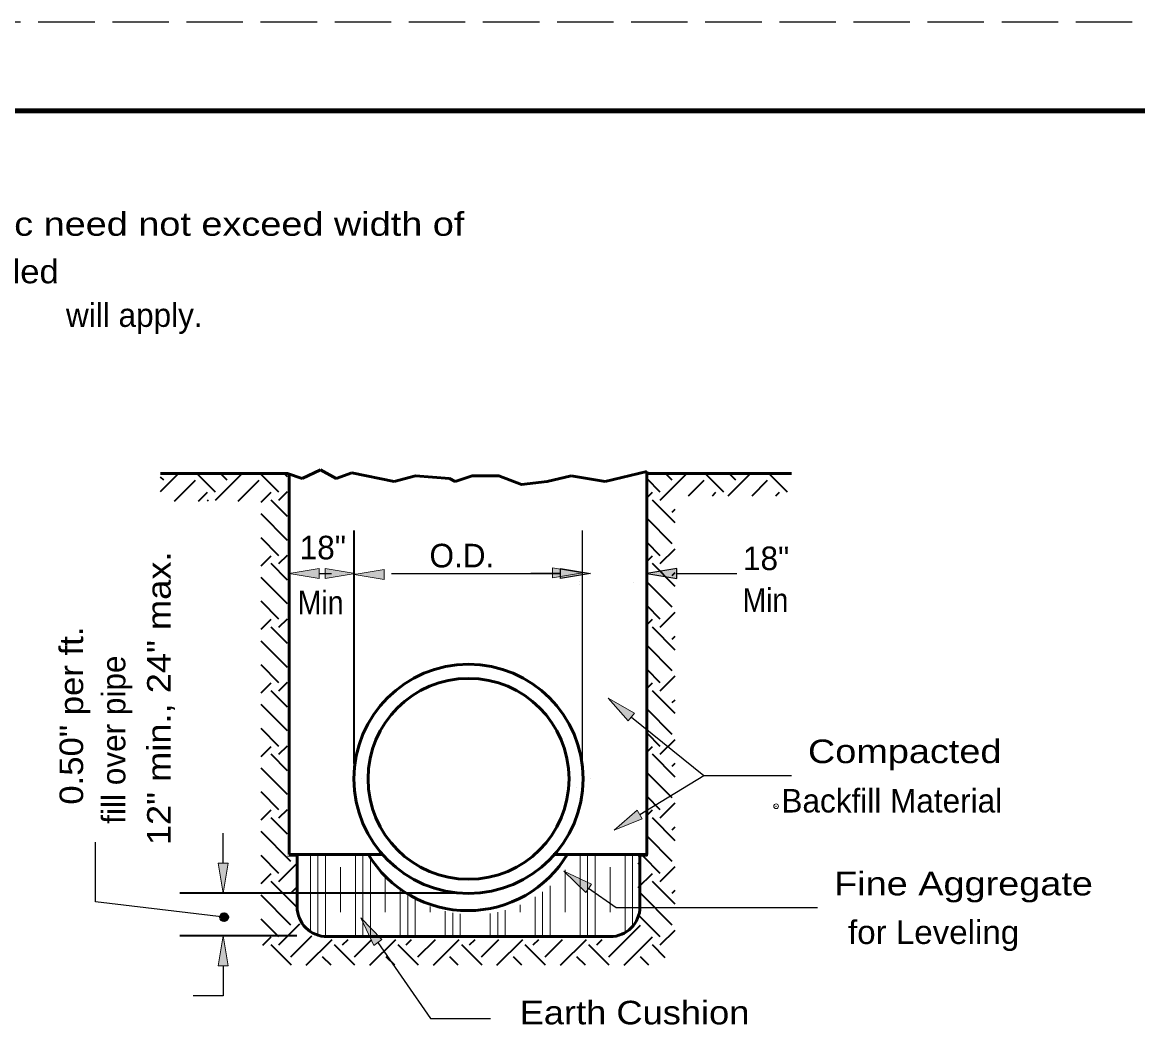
# Model space of a CAD drawing. Extents: x 36.1 to 71.5, y 0.2 to 22.2.
# Drawn here: x 46.27 to 52.56, y 16.56 to 22.21 of the extents above; entities that cross this region are included whole.
import ezdxf

# ---------------------------------------------------------------- set-up
doc = ezdxf.new("R2010")
doc.units = 0
doc.header["$LTSCALE"] = 0.053
doc.header["$PDMODE"] = 32
doc.header["$PDSIZE"] = 0.0265
doc.linetypes.add('LONG_DASHED', pattern=[7.5, 6, -1.5])
for name, color, linetype, lineweight in [('1', 7, 'Continuous', 35), ('3', 7, 'Continuous', 25), ('6', 7, 'Continuous', 13)]:
    doc.layers.add(name, color=color, linetype=linetype, lineweight=lineweight)

msp = doc.modelspace()

# ---------------------------------------------------------------- hatches: boundary and pattern name
at = {"layer": '1'}
for points in [[(47.94108, 19.07442), (47.94108, 19.13083), (47.77208, 19.10275), (47.77208, 19.10275)], [(47.97475, 19.07442), (47.97475, 19.13083), (48.14375, 19.10275), (48.14375, 19.10275)], [(48.30758, 19.06925), (48.30758, 19.12567), (48.13858, 19.09758), (48.13858, 19.09758)], [(49.25708, 19.07958), (49.25708, 19.136), (49.42608, 19.10792), (49.42608, 19.10792)], [(49.30333, 19.07442), (49.30333, 19.13083), (49.47233, 19.10275), (49.47233, 19.10275)], [(49.95933, 19.07442), (49.95933, 19.13083), (49.79033, 19.10275), (49.79033, 19.10275)], [(47.42717, 17.46975), (47.37083, 17.46975), (47.39892, 17.30075), (47.39892, 17.30075)], [(47.42776, 17.16435, 1), (47.38236, 17.16435, 1)], [(47.42717, 16.89042), (47.37083, 16.89042), (47.39892, 17.05942), (47.39892, 17.05942)]]:
    msp.add_hatch(color=256, dxfattribs=at).paths.add_polyline_path(points)
at = {"layer": '3'}
for points in [[(49.68458, 18.272), (49.72008, 18.31583), (49.57083, 18.40017), (49.57083, 18.40017)], [(49.76367, 17.71992), (49.73458, 17.76808), (49.60458, 17.65625), (49.60458, 17.65625)], [(49.44483, 17.30425), (49.47683, 17.35067), (49.32208, 17.424), (49.32208, 17.424)], [(48.24875, 17.00558), (48.295, 17.03783), (48.1755, 17.16042), (48.1755, 17.16042)]]:
    msp.add_hatch(color=256, dxfattribs=at).paths.add_polyline_path(points)

# ---------------------------------------------------------------- linework, layer by layer
at = {"layer": '1', "linetype": 'LONG_DASHED', "lineweight": 25}
msp.add_line((71.33717, 22.21317), (36.13717, 22.21317), dxfattribs=at)
at = {"layer": '1', "lineweight": 158}
msp.add_line((71.25383, 21.71317), (38.75383, 21.71317), dxfattribs=at)
at = {"layer": '1', "lineweight": 53}
for p, q in [((47.0465, 19.66783), (47.76225, 19.66783)), ((47.76225, 19.66783), (47.84583, 19.63867)), ((47.77217, 17.51908), (47.77217, 19.66433)), ((47.84583, 19.63867), (47.94958, 19.68892)), ((47.94958, 19.68892), (48.03733, 19.63867)), ((48.03733, 19.63867), (48.12517, 19.67217)), ((48.12517, 19.67217), (48.3645, 19.622)), ((48.3645, 19.622), (48.48425, 19.65542)), ((48.48425, 19.65542), (48.67575, 19.63867)), ((48.67575, 19.63867), (48.70767, 19.622)), ((48.70767, 19.622), (48.8035, 19.65542)), ((48.8035, 19.65542), (48.95517, 19.65542)), ((48.95517, 19.65542), (49.08283, 19.60517)), ((49.22642, 19.622), (49.36217, 19.65542)), ((49.36217, 19.65542), (49.55367, 19.622)), ((49.55367, 19.622), (49.79033, 19.67925)), ((49.79033, 17.51908), (49.79033, 19.67925)), ((49.79042, 19.66783), (50.60567, 19.66783)), ((49.08283, 19.60517), (49.22642, 19.622)), ((48.29542, 17.51908), (47.77217, 17.51908)), ((47.81692, 17.22392), (47.81692, 17.51908)), ((49.79558, 17.51908), (49.2605, 17.51908)), ((49.75083, 17.51908), (49.75083, 17.22392)), ((49.58183, 17.05492), (47.98592, 17.05492))]:
    msp.add_line(p, q, dxfattribs=at)
at = {"layer": '1'}
for p, q in [((47.0465, 19.56642), (47.14767, 19.66783)), ((47.06467, 19.62967), (47.0465, 19.64792)), ((47.12567, 19.51133), (47.244, 19.62967)), ((47.35608, 19.56242), (47.25058, 19.66783)), ((47.35608, 19.51742), (47.50625, 19.66783)), ((47.42325, 19.62967), (47.385, 19.66783)), ((47.48417, 19.51133), (47.60242, 19.62967)), ((47.71458, 19.56242), (47.60917, 19.66783)), ((47.76225, 19.64908), (47.74358, 19.66783)), ((49.8655, 19.56242), (49.79042, 19.63742)), ((49.8655, 19.51742), (50.01575, 19.66783)), ((49.93275, 19.62967), (49.89458, 19.66783)), ((50.025, 19.54258), (50.11192, 19.62967)), ((50.224, 19.56242), (50.11858, 19.66783)), ((50.24908, 19.54258), (50.37425, 19.66783)), ((50.29125, 19.62967), (50.25308, 19.66783)), ((50.3835, 19.54258), (50.4705, 19.62967)), ((50.5825, 19.56242), (50.47717, 19.66783)), ((47.26025, 19.51133), (47.31125, 19.56242)), ((47.31742, 19.51133), (47.31125, 19.51742)), ((47.61325, 19.50575), (47.66967, 19.56242)), ((47.76225, 19.425), (47.66967, 19.51742)), ((47.71458, 19.51742), (47.76225, 19.56533)), ((49.79042, 19.53208), (49.82075, 19.56242)), ((49.94958, 19.38875), (49.82075, 19.51742)), ((50.1595, 19.54258), (50.17925, 19.56242)), ((50.51792, 19.54258), (50.53775, 19.56242)), ((47.76225, 19.2905), (47.61325, 19.43967)), ((49.93275, 19.45042), (49.94958, 19.46708)), ((49.93275, 19.27108), (49.79042, 19.41342)), ((48.13858, 18.03142), (48.13858, 19.34608)), ((47.71458, 19.20383), (47.61325, 19.30525)), ((49.8655, 19.20383), (49.79042, 19.27883)), ((47.61325, 19.14733), (47.66967, 19.20383)), ((47.71458, 19.15908), (47.76225, 19.20675)), ((49.79042, 19.17358), (49.82075, 19.20383)), ((49.8655, 19.15908), (49.94958, 19.24308)), ((47.76225, 19.0665), (47.66967, 19.15908)), ((49.94958, 19.03025), (49.82075, 19.15908)), ((47.76225, 18.932), (47.61325, 19.08117)), ((49.93275, 19.09183), (49.94958, 19.10867)), ((49.93275, 18.91267), (49.79042, 19.05492)), ((47.71458, 18.84542), (47.61325, 18.94675)), ((49.8655, 18.84542), (49.79042, 18.92033)), ((49.8655, 18.80042), (49.94958, 18.8845)), ((47.61325, 18.78875), (47.66967, 18.84542)), ((47.71458, 18.80042), (47.76225, 18.84825)), ((49.79042, 18.81508), (49.82075, 18.84542)), ((47.76225, 18.708), (47.66967, 18.80042)), ((49.94958, 18.67175), (49.82075, 18.80042)), ((49.93275, 18.73333), (49.94958, 18.75008)), ((47.76225, 18.5735), (47.61325, 18.72267)), ((49.93275, 18.55408), (49.79042, 18.69642)), ((47.71458, 18.48683), (47.61325, 18.58825)), ((49.8655, 18.48683), (49.79042, 18.56192)), ((49.8655, 18.44208), (49.94958, 18.526)), ((47.61325, 18.43025), (47.66967, 18.48683)), ((47.76225, 18.34942), (47.66967, 18.44208)), ((47.71458, 18.44208), (47.76225, 18.48975)), ((49.79042, 18.45667), (49.82075, 18.48683)), ((49.94958, 18.31325), (49.82075, 18.44208)), ((49.93275, 18.37483), (49.94958, 18.39167)), ((47.76225, 18.215), (47.61325, 18.36408)), ((49.93275, 18.19567), (49.79042, 18.33783)), ((47.71458, 18.12833), (47.61325, 18.22975)), ((47.71458, 18.12833), (47.61325, 18.22975)), ((49.8655, 18.12833), (49.79042, 18.20333)), ((47.61325, 18.07175), (47.66967, 18.12833)), ((47.71458, 18.0835), (47.76225, 18.13125)), ((49.79042, 18.09808), (49.82075, 18.12833)), ((49.8655, 18.0835), (49.94958, 18.16758)), ((47.76225, 17.991), (47.66967, 18.0835)), ((49.94958, 17.95475), (49.82075, 18.0835)), ((47.76225, 17.85658), (47.61325, 18.00567)), ((49.93275, 18.01633), (49.94958, 18.03308)), ((49.93275, 17.83708), (49.79042, 17.97942)), ((47.71458, 17.76983), (47.61325, 17.87125)), ((49.8655, 17.76983), (49.79042, 17.84492)), ((49.8655, 17.72492), (49.94958, 17.809)), ((47.61325, 17.71325), (47.66967, 17.76983)), ((47.71458, 17.72492), (47.76225, 17.77275)), ((49.79042, 17.73958), (49.82075, 17.76983)), ((47.76225, 17.63242), (47.66967, 17.72492)), ((49.94958, 17.59625), (49.82075, 17.72492)), ((47.78167, 17.47858), (47.61325, 17.64708)), ((49.93275, 17.47858), (49.79042, 17.62083)), ((49.93275, 17.65783), (49.94958, 17.67458)), ((47.71458, 17.41133), (47.61325, 17.51275)), ((49.8655, 17.41133), (49.76833, 17.50842)), ((47.71458, 17.3665), (47.812, 17.46392)), ((49.74075, 17.46575), (49.7535, 17.47858)), ((49.8655, 17.3665), (49.94958, 17.45058)), ((47.61325, 17.35475), (47.66967, 17.41133)), ((47.812, 17.22425), (47.66967, 17.3665)), ((49.74075, 17.33133), (49.82075, 17.41133)), ((49.94958, 17.23775), (49.82075, 17.3665)), ((48.7415, 17.30075), (47.15558, 17.30075)), ((47.78167, 17.29933), (47.812, 17.3295)), ((49.93275, 17.29933), (49.94958, 17.31608)), ((47.78167, 17.12008), (47.61325, 17.28867)), ((49.93275, 17.12008), (49.7535, 17.29933)), ((49.8655, 17.05283), (49.73842, 17.18)), ((47.71458, 17.05283), (47.61325, 17.15425)), ((47.71458, 17.008), (47.83292, 17.1265)), ((49.57425, 16.94075), (49.7535, 17.12008)), ((47.816, 17.05942), (47.15558, 17.05942)), ((47.62275, 17.00583), (47.66967, 17.05283)), ((47.78167, 16.94075), (47.9005, 17.05942)), ((49.66092, 16.89308), (49.82075, 17.05283)), ((49.8655, 17.008), (49.94958, 17.09208)), ((47.78458, 16.89308), (47.66967, 17.008)), ((47.86842, 16.89308), (48.0145, 17.03908)), ((48.14317, 16.89308), (48.02825, 17.008)), ((48.073, 17.008), (48.10408, 17.03908)), ((48.14025, 16.94075), (48.23858, 17.03908)), ((48.22692, 16.89308), (48.373, 17.03908)), ((48.50158, 16.89308), (48.38667, 17.008)), ((48.43158, 17.008), (48.46258, 17.03908)), ((48.49875, 16.94075), (48.59717, 17.03908)), ((48.5855, 16.89308), (48.7315, 17.03908)), ((48.86017, 16.89308), (48.74525, 17.008)), ((48.79, 17.008), (48.82108, 17.03908)), ((48.85725, 16.94075), (48.95558, 17.03908)), ((48.94392, 16.89308), (49.09, 17.03908)), ((49.21867, 16.89308), (49.10375, 17.008)), ((49.14858, 17.008), (49.17958, 17.03908)), ((49.21575, 16.94075), (49.31408, 17.03908)), ((49.3025, 16.89308), (49.44858, 17.03908)), ((49.57717, 16.89308), (49.46225, 17.008)), ((49.50692, 17.008), (49.53808, 17.03908)), ((49.89292, 16.93583), (49.82075, 17.008)), ((48.00875, 16.89308), (47.961, 16.94075)), ((48.36725, 16.89308), (48.31942, 16.94075)), ((48.72575, 16.89308), (48.67792, 16.94075)), ((49.08425, 16.89308), (49.03658, 16.94075)), ((49.44275, 16.89308), (49.39492, 16.94075)), ((49.80017, 16.89417), (49.7535, 16.94075))]:
    msp.add_line(p, q, dxfattribs=at)
at = {"layer": '1', "lineweight": 25}
for p, q in [((49.42608, 18.03142), (49.42608, 19.34608)), ((47.94117, 19.10275), (48.01075, 19.10275)), ((48.34875, 19.10275), (49.30333, 19.10275)), ((49.30333, 19.10275), (49.13433, 19.10275)), ((49.95933, 19.10275), (50.12833, 19.10275)), ((50.12833, 19.10275), (50.29733, 19.10275)), ((49.79033, 19.03583), (49.79033, 18.85933)), ((47.39892, 17.46975), (47.39892, 17.63875)), ((47.39892, 16.89042), (47.39892, 16.72142)), ((47.39892, 16.72142), (47.22992, 16.72142))]:
    msp.add_line(p, q, dxfattribs=at)
at = {"layer": '1', "lineweight": 13}
for p, q in [((47.77217, 19.02417), (47.77217, 18.85933)), ((47.76225, 17.50842), (47.812, 17.50842)), ((47.89192, 17.08358), (47.89192, 17.51908)), ((47.93417, 17.06308), (47.93417, 17.51908)), ((47.97642, 17.05517), (47.97642, 17.51908)), ((48.14542, 17.05492), (48.14542, 17.51908)), ((48.18758, 17.05492), (48.18758, 17.51908)), ((48.22992, 17.05492), (48.22992, 17.51908)), ((49.41292, 17.05492), (49.41292, 17.51908)), ((49.45517, 17.05492), (49.45517, 17.51908)), ((49.49742, 17.05492), (49.49742, 17.51908)), ((49.66642, 17.07767), (49.66642, 17.51908)), ((49.70858, 17.11233), (49.70858, 17.51908)), ((49.74075, 17.50842), (49.79042, 17.50842)), ((48.06092, 17.19242), (48.06092, 17.44583)), ((49.32842, 17.19242), (49.32842, 17.43183)), ((49.58192, 17.19242), (49.58192, 17.44583)), ((48.31442, 17.19242), (48.31442, 17.40583)), ((48.39892, 17.05492), (48.39892, 17.32408)), ((49.20158, 17.05492), (49.20158, 17.30792)), ((49.24392, 17.05492), (49.24392, 17.34208)), ((48.44117, 17.05492), (48.44117, 17.29267)), ((48.48342, 17.05492), (48.48342, 17.26608)), ((49.15942, 17.05492), (49.15942, 17.279)), ((48.56792, 17.19242), (48.56792, 17.22525)), ((48.65242, 17.05492), (48.65242, 17.19792)), ((48.69458, 17.05492), (48.69458, 17.18892)), ((48.73692, 17.05492), (48.73692, 17.18275)), ((48.90592, 17.05492), (48.90592, 17.1855)), ((48.94817, 17.05492), (48.94817, 17.19317)), ((48.99042, 17.05492), (48.99042, 17.20367)), ((49.07492, 17.19242), (49.07492, 17.23425))]:
    msp.add_line(p, q, dxfattribs=at)
for points in [[(47.94108, 19.07442), (47.94108, 19.13083), (47.77208, 19.10275), (47.77208, 19.10275)], [(47.97475, 19.07442), (47.97475, 19.13083), (48.14375, 19.10275), (48.14375, 19.10275)], [(48.30758, 19.06925), (48.30758, 19.12567), (48.13858, 19.09758), (48.13858, 19.09758)], [(49.25708, 19.07958), (49.25708, 19.136), (49.42608, 19.10792), (49.42608, 19.10792)], [(47.42717, 17.46975), (47.37083, 17.46975), (47.39892, 17.30075), (47.39892, 17.30075)], [(47.42717, 16.89042), (47.37083, 16.89042), (47.39892, 17.05942), (47.39892, 17.05942)]]:
    msp.add_lwpolyline(points, close=True, dxfattribs=at)
at = {"layer": '1', "lineweight": 25}
for points in [[(49.30333, 19.07442), (49.30333, 19.13083), (49.47233, 19.10275), (49.47233, 19.10275)], [(49.95933, 19.07442), (49.95933, 19.13083), (49.79033, 19.10275), (49.79033, 19.10275)]]:
    msp.add_lwpolyline(points, close=True, dxfattribs=at)
msp.add_lwpolyline([(47.40508, 17.16442), (46.67992, 17.2505), (46.67992, 17.587)], dxfattribs=at)
at = {"layer": '1', "lineweight": 53}
for radius in [0.64629, 0.56675]:
    msp.add_circle((48.78393, 17.94493), radius, dxfattribs=at)
at = {"layer": '1'}
msp.add_circle((47.40506, 17.16435), 0.02269, dxfattribs=at)
at = {"layer": '1', "lineweight": 53}
for centre, radius, start, end in [((48.77986, 17.8571), 0.65572, 210.90644, 329.22554), ((47.98586, 17.22395), 0.169, 180, 270), ((49.58178, 17.22395), 0.169, 270, 0)]:
    msp.add_arc(centre, radius, start, end, dxfattribs=at)
at = {"layer": '3', "lineweight": 13}
msp.add_line((49.71158, 19.0525), (49.71167, 19.0525), dxfattribs=at)
at = {"layer": '3'}
msp.add_line((49.74917, 17.744), (50.11108, 17.96342), dxfattribs=at)
at = {"layer": '3', "lineweight": 13}
for points in [[(49.68458, 18.272), (49.72008, 18.31583), (49.57083, 18.40017), (49.57083, 18.40017)], [(49.76367, 17.71992), (49.73458, 17.76808), (49.60458, 17.65625), (49.60458, 17.65625)], [(49.44483, 17.30425), (49.47683, 17.35067), (49.32208, 17.424), (49.32208, 17.424)], [(48.24875, 17.00558), (48.295, 17.03783), (48.1755, 17.16042), (48.1755, 17.16042)]]:
    msp.add_lwpolyline(points, close=True, dxfattribs=at)
at = {"layer": '3'}
for points in [[(49.70233, 18.29392), (50.11108, 17.96342), (50.60625, 17.96342)], [(49.46092, 17.32742), (49.61592, 17.21958), (50.75258, 17.21958)], [(48.27192, 17.02175), (48.56942, 16.59375), (48.90692, 16.59375)]]:
    msp.add_lwpolyline(points, dxfattribs=at)
at = {"layer": '6'}
for p, q in [((47.77217, 19.10867), (47.77225, 19.10867)), ((48.17975, 19.10275), (48.17992, 19.10275)), ((49.47233, 19.10275), (49.47258, 19.10275)), ((49.40925, 19.05683), (49.40942, 19.05683)), ((49.40925, 19.04417), (49.40942, 19.04417)), ((48.17975, 17.94692), (48.17992, 17.94692)), ((48.17975, 17.94692), (48.17992, 17.94692)), ((49.47233, 17.94692), (49.47258, 17.94692)), ((49.39025, 17.89467), (49.39033, 17.89467)), ((48.826, 17.30075), (48.82608, 17.30075)), ((47.39892, 17.05942), (47.39917, 17.05942)), ((47.9005, 17.05942), (47.90058, 17.05942))]:
    msp.add_line(p, q, dxfattribs=at)
at = {"layer": '6', "lineweight": 25}
for p, q in [((49.79033, 19.12042), (49.79042, 19.12042)), ((49.79033, 19.10275), (49.79042, 19.10275)), ((49.47233, 17.94692), (49.47258, 17.94692))]:
    msp.add_line(p, q, dxfattribs=at)
at = {"layer": '6'}
msp.add_point((50.51892, 17.79008), dxfattribs=at)

# ---------------------------------------------------------------- texts
at = {"layer": '3'}
for s, width, p in [('arc need not exceed width of', 1.2, (46.03142, 21.00892)), ('plate pipe is first assembled', 1.1, (44.05875, 20.74075)), ('Min', 0.9, (47.82075, 18.87292)), ('Min', 0.9, (50.32917, 18.88717)), ('Compacted', 1.2, (50.69817, 18.03375)), ('Fine Aggregate', 1.2, (50.84592, 17.2875)), ('for Leveling', 1.05, (50.92425, 17.01342)), ('Earth Cushion', 1.15, (49.072, 16.55992))]:
    msp.add_text(s, height=0.133, dxfattribs=dict(at, width=width)).set_placement(p)
for s, p in [('will apply.', (46.51325, 20.49492)), ('18"', (47.83158, 19.18325)), ('O.D.', (48.5635, 19.13808)), ('18"', (50.33167, 19.12267)), ('Backfill Material', (50.54858, 17.75517))]:
    msp.add_text(s, height=0.133, dxfattribs=at).set_placement(p)
for s, width, p in [('12" min., 24" max.', 1.15, (47.10383, 17.57075)), ('0.50" per ft. ', 1.1, (46.60992, 17.79942))]:
    msp.add_text(s, height=0.133, rotation=90, dxfattribs=dict(at, width=width)).set_placement(p)
msp.add_text(' fill over pipe', height=0.133, rotation=90, dxfattribs=at).set_placement((46.84808, 17.64242))

doc.saveas('drawing.dxf')
